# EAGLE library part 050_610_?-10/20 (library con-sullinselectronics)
.050 DIP EDGE CARD CONNECTOR .050 [1.27mm] CONTACT CENTERS .610" INSULATEOR HEIGHT Source: .050 DIP EDGE CARD.pdf
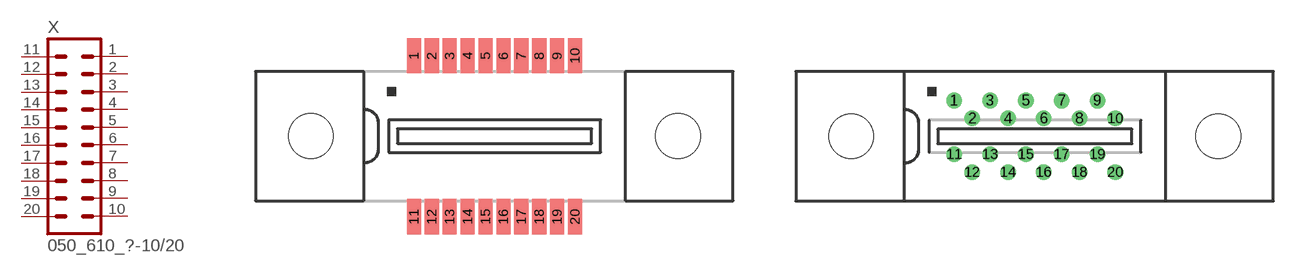
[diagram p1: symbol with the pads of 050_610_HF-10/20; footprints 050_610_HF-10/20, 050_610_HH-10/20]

Designator prefix X

## 050_610_HF-10/20 (OC_FARNELL: unknown; OC_NEWARK: unknown)  [050_610_HF-10/20]
1  1  pas
2  2  pas
3  3  pas
4  4  pas
5  5  pas
6  6  pas
7  7  pas
8  8  pas
9  9  pas
10  10  pas
11  11  pas
12  12  pas
13  13  pas
14  14  pas
15  15  pas
16  16  pas
17  17  pas
18  18  pas
19  19  pas
20  20  pas

## 050_610_HH-10/20 (OC_FARNELL: unknown; OC_NEWARK: unknown)  [050_610_HH-10/20]
Pads as for 050_610_HF-10/20

## Footprint 050_610_HF-10/20 (pad centres in mm)
.050 DIP EDGE CARD CONNECTOR SURFACE MOUNT .050 [1.27mm] CONTACT CENTERS .610" INSULATEOR HEIGHT Source: .050 DIP EDGE CARD.pdf
smd 1 x 2.5: 1 -5.715,5.715; 2 -4.445,5.715; 3 -3.175,5.715; 4 -1.905,5.715; 5 -0.635,5.715; 6 0.635,5.715; 7 1.905,5.715; 8 3.175,5.715; 9 4.445,5.715; 10 5.715,5.715; 11 -5.715,-5.715; 12 -4.445,-5.715; 13 -3.175,-5.715; 14 -1.905,-5.715; 15 -0.635,-5.715; 16 0.635,-5.715; 17 1.905,-5.715; 18 3.175,-5.715; 19 4.445,-5.715; 20 5.715,-5.715
hole 3.18 at -13.03,0
hole 3.18 at 13.03,0

## Footprint 050_610_HH-10/20 (pad centres in mm)
.050 DIP EDGE CARD CONNECTOR STAGGERED DIP SOLDER .050 [1.27mm] CONTACT CENTERS .610" INSULATEOR HEIGHT Source: .050 DIP EDGE CARD.pdf
drill 0.6 pad 1 round: 1 -5.715,2.54; 2 -4.445,1.27; 3 -3.175,2.54; 4 -1.905,1.27; 5 -0.635,2.54; 6 0.635,1.27; 7 1.905,2.54; 8 3.175,1.27; 9 4.445,2.54; 10 5.715,1.27; 11 -5.715,-1.27; 12 -4.445,-2.54; 13 -3.175,-1.27; 14 -1.905,-2.54; 15 -0.635,-1.27; 16 0.635,-2.54; 17 1.905,-1.27; 18 3.175,-2.54; 19 4.445,-1.27; 20 5.715,-2.54
hole 3.18 at -13.03,0
hole 3.18 at 13.03,0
